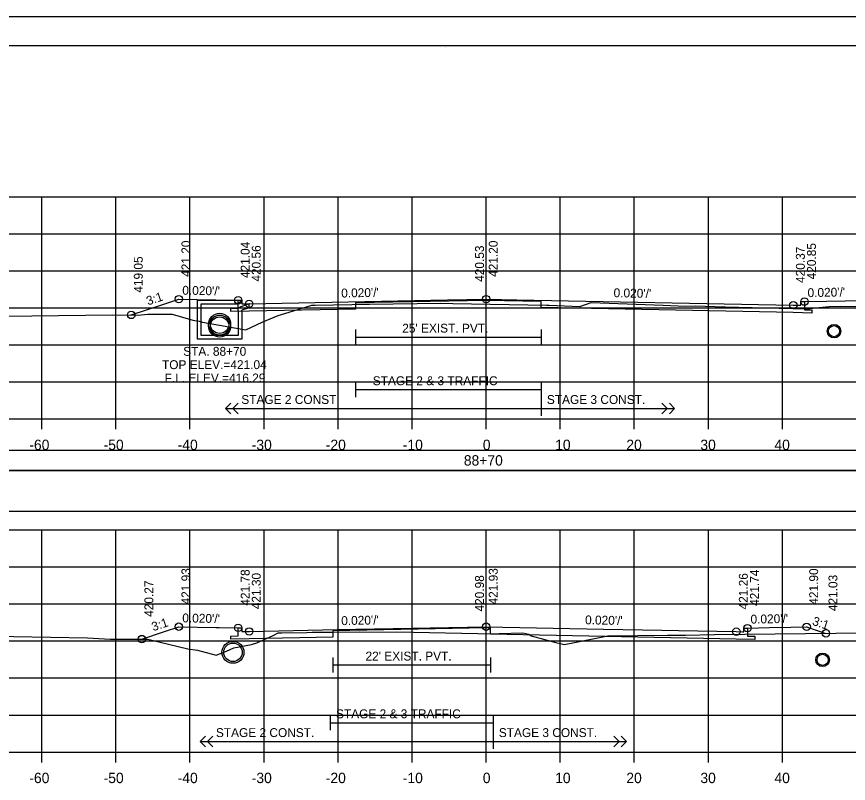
# Model space of a CAD drawing. Extents: x 1371057 to 1372761, y 380005 to 390517.
# Drawn here: x 1371164.1 to 1371276.4, y 388861.7 to 388965.3 of the extents above; entities that cross this region are included whole.
import ezdxf

# ---------------------------------------------------------------- set-up
doc = ezdxf.new("R2010")
doc.units = 0
for name, color, linetype in [('R_Alt Surface', 7, 'Continuous'), ('R_Axis', 7, 'Continuous'), ('R_Axis Annot', 7, 'Continuous'), ('R_Border', 7, 'Continuous'), ('R_Detour', 7, 'Continuous'), ('R_Dimension', 7, 'Continuous'), ('R_Exist Surface', 7, 'Continuous'), ('R_Fin Surface', 7, 'Continuous'), ('R_Grid', 7, 'Continuous'), ('R_No Plot', 7, 'Continuous'), ('R_Striping', 7, 'Continuous'), ('R_Water', 7, 'Continuous'), ('R_Water Annot', 7, 'Continuous'), ('R_Xsect Elev', 7, 'Continuous'), ('R_Xsect Slope', 7, 'Continuous')]:
    doc.layers.add(name, color=color, linetype=linetype)

msp = doc.modelspace()

# ---------------------------------------------------------------- linework, layer by layer
for p, q in [((1371188.53, 388926.95), (1371194.28, 388926.95)), ((1371188.53, 388925.45), (1371188.53, 388926.95)), ((1371194.36, 388926.79), (1371194.28, 388926.95)), ((1371189.03, 388925.45), (1371189.03, 388926.45)), ((1371189.03, 388926.45), (1371194.03, 388926.45)), ((1371194.36, 388926.79), (1371194.03, 388926.45)), ((1371195.53, 388926.47), (1371194.03, 388925.95)), ((1371194.03, 388925.45), (1371194.03, 388925.95)), ((1371195.53, 388925.95), (1371194.53, 388925.6)), ((1371194.53, 388925.45), (1371194.53, 388925.6))]:
    msp.add_line(p, q)
msp.add_lwpolyline([(1371195.53, 388925.95), (1371195.53, 388926.47)])
at = {"layer": 'R_Alt Surface'}
for points in [[(1371270.5, 388926.77), (1371270.5, 388925.68), (1371271.5, 388925.66), (1371271.5, 388925.23), (1371269, 388925.28), (1371234.97, 388925.97), (1371234.97, 388926.8), (1371227.53, 388926.94), (1371209.9, 388926.59), (1371209.9, 388925.76), (1371195.53, 388925.47), (1371193.03, 388925.42), (1371193.03, 388925.85), (1371194.03, 388925.87), (1371194.03, 388926.95)], [(1371209.9, 388922.98), (1371209.9, 388920.98)], [(1371234.97, 388922.98), (1371234.97, 388920.98)], [(1371209.9, 388921.98), (1371234.97, 388921.98)], [(1371262.8, 388882.66), (1371262.8, 388881.58), (1371263.8, 388881.56), (1371263.8, 388881.13), (1371261.3, 388881.18), (1371228.12, 388881.84), (1371228.12, 388882.67), (1371227.53, 388882.68), (1371206.82, 388882.27), (1371206.82, 388881.44), (1371195.53, 388881.21), (1371193.03, 388881.16), (1371193.03, 388881.59), (1371194.03, 388881.61), (1371194.03, 388882.69)], [(1371206.82, 388878.68), (1371206.82, 388876.68)], [(1371228.12, 388878.68), (1371228.12, 388876.68)], [(1371206.82, 388877.68), (1371228.12, 388877.68)]]:
    msp.add_lwpolyline(points, dxfattribs=at)
at = {"layer": 'R_Axis'}
for p, q in [((1371077.53, 388910.92), (1371377.53, 388910.92)), ((1371167.53, 388909.52), (1371167.53, 388910.92)), ((1371177.53, 388909.52), (1371177.53, 388910.92)), ((1371187.53, 388909.52), (1371187.53, 388910.92)), ((1371197.53, 388909.52), (1371197.53, 388910.92)), ((1371207.53, 388909.52), (1371207.53, 388910.92)), ((1371217.53, 388909.52), (1371217.53, 388910.92)), ((1371227.53, 388909.52), (1371227.53, 388910.92)), ((1371237.53, 388909.52), (1371237.53, 388910.92)), ((1371247.53, 388909.52), (1371247.53, 388910.92)), ((1371257.53, 388909.52), (1371257.53, 388910.92)), ((1371267.53, 388909.52), (1371267.53, 388910.92)), ((1371077.53, 388865.92), (1371377.53, 388865.92)), ((1371167.53, 388864.52), (1371167.53, 388865.92)), ((1371177.53, 388864.52), (1371177.53, 388865.92)), ((1371187.53, 388864.52), (1371187.53, 388865.92)), ((1371197.53, 388864.52), (1371197.53, 388865.92)), ((1371207.53, 388864.52), (1371207.53, 388865.92)), ((1371217.53, 388864.52), (1371217.53, 388865.92)), ((1371227.53, 388864.52), (1371227.53, 388865.92)), ((1371237.53, 388864.52), (1371237.53, 388865.92)), ((1371247.53, 388864.52), (1371247.53, 388865.92)), ((1371257.53, 388864.52), (1371257.53, 388865.92)), ((1371267.53, 388864.52), (1371267.53, 388865.92))]:
    msp.add_line(p, q, dxfattribs=at)
at = {"layer": 'R_Border'}
for p, q in [((1371069.53, 388961.38), (1371385.71, 388961.38)), ((1371222.05, 388961.12), (1371222.05, 388961.12)), ((1371222.05, 388961.12), (1371222.05, 388961.12))]:
    msp.add_line(p, q, dxfattribs=at)
at = {"layer": 'R_Detour'}
msp.add_lwpolyline([(1371074.38, 388903.96), (1371380.69, 388903.96), (1371380.69, 388906.67), (1371074.38, 388906.67)], close=True, dxfattribs=at)
at = {"layer": 'R_Dimension'}
msp.add_lwpolyline([(1371074.38, 388898.44), (1371380.69, 388898.44), (1371380.69, 388903.96), (1371074.38, 388903.96)], close=True, dxfattribs=at)
at = {"layer": 'R_Exist Surface'}
for points in [[(1371158.88, 388924.74), (1371177, 388925), (1371180.47, 388924.96), (1371181.86, 388925.06), (1371185.13, 388925.07), (1371187.93, 388924.28), (1371188.75, 388924.14), (1371189.23, 388923.99), (1371195.05, 388922.95), (1371197.29, 388924.01), (1371199.45, 388924.91), (1371203.12, 388926.04), (1371204, 388926.27), (1371204.44, 388926.29), (1371209.37, 388926.38), (1371209.91, 388926.41), (1371210.02, 388926.42), (1371211.78, 388926.44), (1371221.38, 388926.56), (1371223, 388926.53), (1371235.66, 388926.29), (1371236.03, 388926.28), (1371240.19, 388926.13), (1371240.2, 388926.13), (1371240.31, 388926.16), (1371241.71, 388926.66), (1371251.41, 388926.29), (1371254.43, 388926.17), (1371255.74, 388926.18), (1371259.8, 388926.07), (1371270.75, 388925.8), (1371273.83, 388926.1), (1371275.38, 388926.15), (1371310.88, 388925.4)], [(1371158.64, 388881.62), (1371173.67, 388881.35), (1371176.77, 388881.17), (1371181.64, 388881.18), (1371181.78, 388881.18), (1371182.01, 388881.13), (1371187.23, 388879.87), (1371188.54, 388879.67), (1371191.06, 388878.99), (1371192.44, 388879.53), (1371193.46, 388879.98), (1371195.83, 388880.46), (1371196.56, 388880.66), (1371198.74, 388881.68), (1371199.44, 388882.03), (1371199.55, 388882.04), (1371199.94, 388882.04), (1371203.32, 388882.06), (1371204.03, 388882.1), (1371204.21, 388882.11), (1371206.89, 388882.13), (1371210.43, 388882.14), (1371217.72, 388882.12), (1371226.42, 388881.92), (1371228.71, 388881.87), (1371229.3, 388881.92), (1371232.49, 388882.02), (1371233.28, 388881.85), (1371233.58, 388881.63), (1371236.93, 388880.71), (1371238.04, 388880.44), (1371239.21, 388880.67), (1371243.96, 388881.61), (1371252, 388881.7), (1371253.51, 388881.72), (1371254.46, 388881.72), (1371258.36, 388881.78), (1371278.84, 388882.01)]]:
    msp.add_lwpolyline(points, dxfattribs=at)
at = {"layer": 'R_Fin Surface'}
for points in [[(1371179.6, 388924.97), (1371183.88, 388926.4), (1371186.03, 388927.11), (1371191.03, 388927.01), (1371194.03, 388926.95), (1371194.53, 388926.95), (1371194.54, 388926.45), (1371194.99, 388926.46), (1371195.53, 388926.47), (1371222.31, 388927.01), (1371227.53, 388927.11), (1371231.67, 388927.03), (1371269, 388926.29), (1371270, 388926.27), (1371270, 388926.49), (1371270, 388926.77), (1371270.5, 388926.77), (1371273.5, 388926.83), (1371278.5, 388926.93), (1371281.19, 388926.03)], [(1371181.03, 388881.18), (1371184.11, 388882.21), (1371186.03, 388882.85), (1371186.03, 388882.85), (1371191.03, 388882.75), (1371191.46, 388882.74), (1371194.03, 388882.69), (1371194.03, 388882.69), (1371194.28, 388882.69), (1371194.53, 388882.69), (1371194.54, 388882.19), (1371195.53, 388882.21), (1371195.55, 388882.21), (1371207.4, 388882.45), (1371227.53, 388882.85), (1371243.37, 388882.53), (1371251.26, 388882.38), (1371253.51, 388882.33), (1371261.29, 388882.18), (1371261.3, 388882.18), (1371262.14, 388882.16), (1371262.3, 388882.16), (1371262.3, 388882.66), (1371262.66, 388882.66), (1371262.8, 388882.66), (1371264.28, 388882.69), (1371265.8, 388882.72), (1371265.8, 388882.72), (1371268.65, 388882.77), (1371270.8, 388882.82), (1371273.4, 388881.95)]]:
    msp.add_lwpolyline(points, dxfattribs=at)
at = {"layer": 'R_Grid'}
for p, q in [((1371077.53, 388940.92), (1371377.53, 388940.92)), ((1371167.53, 388910.92), (1371167.53, 388940.92)), ((1371177.53, 388910.92), (1371177.53, 388940.92)), ((1371187.53, 388910.92), (1371187.53, 388940.92)), ((1371197.53, 388910.92), (1371197.53, 388940.92)), ((1371207.53, 388910.92), (1371207.53, 388940.92)), ((1371217.53, 388910.92), (1371217.53, 388940.92)), ((1371227.53, 388910.92), (1371227.53, 388940.92)), ((1371237.53, 388910.92), (1371237.53, 388940.92)), ((1371247.53, 388910.92), (1371247.53, 388940.92)), ((1371257.53, 388910.92), (1371257.53, 388940.92)), ((1371267.53, 388910.92), (1371267.53, 388940.92)), ((1371077.53, 388935.92), (1371377.53, 388935.92)), ((1371077.53, 388930.92), (1371377.53, 388930.92)), ((1371077.53, 388925.92), (1371377.53, 388925.92)), ((1371077.53, 388920.92), (1371377.53, 388920.92)), ((1371077.53, 388915.92), (1371377.53, 388915.92)), ((1371077.53, 388910.92), (1371377.53, 388910.92)), ((1371077.53, 388895.92), (1371377.53, 388895.92)), ((1371167.53, 388865.92), (1371167.53, 388895.92)), ((1371177.53, 388865.92), (1371177.53, 388895.92)), ((1371187.53, 388865.92), (1371187.53, 388895.92)), ((1371197.53, 388865.92), (1371197.53, 388895.92)), ((1371207.53, 388865.92), (1371207.53, 388895.92)), ((1371217.53, 388865.92), (1371217.53, 388895.92)), ((1371227.53, 388865.92), (1371227.53, 388895.92)), ((1371237.53, 388865.92), (1371237.53, 388895.92)), ((1371247.53, 388865.92), (1371247.53, 388895.92)), ((1371257.53, 388865.92), (1371257.53, 388895.92)), ((1371267.53, 388865.92), (1371267.53, 388895.92)), ((1371077.53, 388890.92), (1371377.53, 388890.92)), ((1371077.53, 388885.92), (1371377.53, 388885.92)), ((1371077.53, 388880.92), (1371377.53, 388880.92)), ((1371077.53, 388875.92), (1371377.53, 388875.92)), ((1371077.53, 388870.92), (1371377.53, 388870.92)), ((1371077.53, 388865.92), (1371377.53, 388865.92))]:
    msp.add_line(p, q, dxfattribs=at)
at = {"layer": 'R_No Plot'}
msp.add_line((1371057.13, 388965.27), (1371390.46, 388965.27), dxfattribs=at)
for points in [[(1371057.12, 388965.27), (1371390.46, 388965.27), (1371390.46, 388751.93), (1371057.12, 388751.93)], [(1371303.45, 388961.38), (1371323.07, 388961.38), (1371323.07, 388951.5), (1371339.18, 388951.5), (1371362.38, 388951.5), (1371362.5, 388923.34), (1371385.71, 388923.34), (1371385.71, 388755.92), (1371069.53, 388755.92), (1371069.53, 388961.38)]]:
    msp.add_lwpolyline(points, close=True, dxfattribs=at)
for centre, radius in [((1371186.03, 388927.11), 0.5), ((1371194.03, 388926.95), 0.5), ((1371195.53, 388926.47), 0.5), ((1371227.53, 388927.11), 0.5), ((1371270.5, 388926.77), 0.5), ((1371269, 388926.29), 0.5), ((1371179.6, 388924.97), 0.5), ((1371191.53, 388923.71), 1.48), ((1371191.53, 388923.46), 1.48), ((1371274.5, 388922.78), 0.917), ((1371186.03, 388882.85), 0.5), ((1371194.03, 388882.69), 0.5), ((1371227.53, 388882.85), 0.5), ((1371262.8, 388882.66), 0.5), ((1371270.8, 388882.82), 0.5), ((1371195.53, 388882.21), 0.5), ((1371261.3, 388882.18), 0.5), ((1371273.4, 388881.95), 0.5), ((1371181.03, 388881.18), 0.5), ((1371193.33, 388879.39), 1.48), ((1371272.95, 388878.37), 0.917)]:
    msp.add_circle(centre, radius, dxfattribs=at)
at = {"layer": 'R_Striping'}
for p, q in [((1371209.9, 388915.88), (1371209.9, 388913.88)), ((1371234.97, 388915.88), (1371234.97, 388911.34)), ((1371209.9, 388914.88), (1371234.97, 388914.88)), ((1371192.33, 388912.34), (1371193.04, 388913.05)), ((1371192.33, 388912.34), (1371234.97, 388912.34)), ((1371193.04, 388911.63), (1371192.33, 388912.34)), ((1371193.33, 388912.34), (1371194.04, 388913.05)), ((1371194.04, 388911.63), (1371193.33, 388912.34)), ((1371234.97, 388912.34), (1371252.97, 388912.34)), ((1371235, 388912.34), (1371245, 388912.34)), ((1371251.97, 388912.34), (1371251.26, 388913.05)), ((1371251.26, 388911.63), (1371251.97, 388912.34)), ((1371252.97, 388912.34), (1371252.26, 388913.05)), ((1371252.26, 388911.63), (1371252.97, 388912.34)), ((1371206.47, 388870.88), (1371206.47, 388868.88)), ((1371228.48, 388870.88), (1371228.48, 388866.34)), ((1371206.47, 388869.88), (1371228.48, 388869.88)), ((1371188.9, 388867.34), (1371189.61, 388868.05)), ((1371188.9, 388867.34), (1371228.48, 388867.34)), ((1371189.61, 388866.63), (1371188.9, 388867.34)), ((1371189.9, 388867.34), (1371190.61, 388868.05)), ((1371190.61, 388866.63), (1371189.9, 388867.34)), ((1371228.48, 388867.34), (1371246.48, 388867.34)), ((1371228.51, 388867.34), (1371238.51, 388867.34)), ((1371245.48, 388867.34), (1371244.77, 388868.05)), ((1371244.77, 388866.63), (1371245.48, 388867.34)), ((1371246.48, 388867.34), (1371245.77, 388868.05)), ((1371245.77, 388866.63), (1371246.48, 388867.34))]:
    msp.add_line(p, q, dxfattribs=at)
at = {"layer": 'R_Water'}
for points in [[(1371194.53, 388925.45), (1371194.53, 388921.71), (1371191.53, 388921.71), (1371188.53, 388921.71), (1371188.53, 388925.45)], [(1371194.03, 388925.45), (1371194.03, 388922.21), (1371191.53, 388922.21), (1371189.03, 388922.21), (1371189.03, 388925.45)]]:
    msp.add_lwpolyline(points, dxfattribs=at)
for centre, radius in [((1371191.53, 388923.71), 1.25), ((1371191.53, 388923.46), 1.25), ((1371274.5, 388922.78), 0.75), ((1371193.33, 388879.39), 1.25), ((1371272.95, 388878.37), 0.75)]:
    msp.add_circle(centre, radius, dxfattribs=at)
at = {"layer": 'R_Xsect Elev'}
for p, q in [((1371227.53, 388926.44), (1371227.53, 388936.44)), ((1371227.53, 388881.9), (1371227.53, 388891.9))]:
    msp.add_line(p, q, dxfattribs=at)

# ---------------------------------------------------------------- texts
at = {"layer": 'R_Axis Annot'}
for s, p in [('-60', (1371165.84, 388906.72)), ('-50', (1371175.87, 388906.72)), ('-40', (1371185.87, 388906.72)), ('-30', (1371195.87, 388906.72)), ('-20', (1371205.87, 388906.72)), ('-10', (1371216.27, 388906.72)), ('0', (1371227.07, 388906.72)), ('10', (1371236.84, 388906.72)), ('20', (1371246.45, 388906.72)), ('30', (1371256.45, 388906.72)), ('40', (1371266.45, 388906.72)), ('88+70', (1371224.51, 388904.62)), ('-60', (1371165.84, 388861.72)), ('-50', (1371175.87, 388861.72)), ('-40', (1371185.87, 388861.72)), ('-30', (1371195.87, 388861.72)), ('-20', (1371205.87, 388861.72)), ('-10', (1371216.27, 388861.72)), ('0', (1371227.07, 388861.72)), ('10', (1371236.84, 388861.72)), ('20', (1371246.45, 388861.72)), ('30', (1371256.45, 388861.72)), ('40', (1371266.45, 388861.72))]:
    msp.add_text(s, height=1.4, dxfattribs=at).set_placement(p)
at = {"layer": 'R_Striping'}
for s, p in [('STAGE 2 & 3 TRAFFIC', (1371212.21, 388915.48)), ('STAGE 2 CONST.', (1371194.46, 388912.94)), ('STAGE 3 CONST.', (1371235.72, 388912.94)), ('STAGE 2 & 3 TRAFFIC', (1371207.25, 388870.48)), ('STAGE 2 CONST.', (1371191.03, 388867.94)), ('STAGE 3 CONST.', (1371229.23, 388867.94))]:
    msp.add_text(s, height=1.2, dxfattribs=at).set_placement(p)
at = {"layer": 'R_Water'}
for s, p in [("25' EXIST. PVT.", (1371216.19, 388922.58)), ("22' EXIST. PVT.", (1371211.23, 388878.28))]:
    msp.add_text(s, height=1.2, dxfattribs=at).set_placement(p)
at = {"layer": 'R_Water Annot'}
for s, p in [('STA. 88+70', (1371186.61, 388919.45)), ('TOP ELEV.=421.04', (1371183.75, 388917.65)), ('F.L. ELEV.=416.29', (1371184.11, 388915.85))]:
    msp.add_text(s, height=1.2, dxfattribs=at).set_placement(p)
at = {"layer": 'R_Xsect Elev'}
for s, p in [('421.20', (1371187.58, 388930.11)), ('421.04', (1371195.58, 388929.95)), ('421.20', (1371229.08, 388930.11)), ('420.56', (1371197.08, 388929.47)), ('420.53', (1371227.23, 388929.44)), ('420.37', (1371270.55, 388929.29)), ('420.85', (1371272.05, 388929.77)), ('419.05', (1371181.15, 388927.97)), ('421.93', (1371187.58, 388885.85)), ('421.78', (1371195.58, 388885.69)), ('421.30', (1371197.08, 388885.21)), ('420.98', (1371227.23, 388884.9)), ('421.93', (1371229.08, 388885.85)), ('421.26', (1371262.85, 388885.18)), ('421.74', (1371264.35, 388885.66)), ('421.90', (1371272.35, 388885.82)), ('421.03', (1371274.95, 388884.95)), ('420.27', (1371182.58, 388884.18))]:
    msp.add_text(s, height=1.2, rotation=90, dxfattribs=at).set_placement(p)
at = {"layer": 'R_Xsect Slope'}
for s, rotation, p in [('3:1', 18.4395, (1371181.87, 388926.25)), ("0.020'/'", 358.8542, (1371186.48, 388927.71)), ("0.020'/'", 1.1457, (1371207.96, 388927.32)), ("0.020'/'", 358.8548, (1371244.72, 388927.37)), ("0.020'/'", 1.1458, (1371270.93, 388927.37)), ("0.020'/'", 358.8542, (1371186.48, 388883.44)), ("0.020'/'", 1.1458, (1371207.96, 388883.06)), ("0.020'/'", 358.8532, (1371240.87, 388883.18)), ("0.020'/'", 1.1457, (1371263.23, 388883.26)), ('3:1', 341.5733, (1371271.47, 388883.12)), ('3:1', 18.4345, (1371182.58, 388882.23))]:
    msp.add_text(s, height=1.2, rotation=rotation, dxfattribs=at).set_placement(p)

doc.saveas('drawing.dxf')
